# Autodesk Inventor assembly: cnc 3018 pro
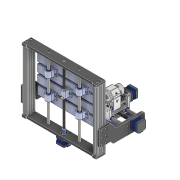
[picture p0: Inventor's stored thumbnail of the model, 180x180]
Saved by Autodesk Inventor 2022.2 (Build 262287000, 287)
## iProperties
Created: 2023-04
Part Number: cnc 3018 pro
Description: STEP AP214
Document SubType Name: Assembly
Designer: 18907419
Sending System: SolidWorks 2023
Preprocessor: SwSTEP 2.0
Title: Baugruppe - Original.STEP
Revision Number: ANY
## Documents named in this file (37)
- C:\Users\18907419\Desktop\cnc 3018\cnc 3018 pro.iam
- C:\Users\18907419\Desktop\cnc 3018\Original - Nutenstein klein M5.ipt
- C:\Users\18907419\Desktop\cnc 3018\Original - Nutenstein M5.ipt
- C:\Users\18907419\Desktop\cnc 3018\Original - Zylinderkopfschraube M4x30.ipt
- C:\Users\18907419\Desktop\cnc 3018\Original - Madenschraube M4x4.ipt
- C:\Users\18907419\Desktop\cnc 3018\Original - Zylinderkopfschraube M3x14.ipt
- C:\Users\18907419\Desktop\cnc 3018\Original - Zylinderkopfschraube M3x20.ipt
- C:\Users\18907419\Desktop\cnc 3018\Original - Zylinderkopfschraube M5x16.ipt
- C:\Users\18907419\Desktop\cnc 3018\Original - Aluminium Profil X.ipt
- C:\Users\18907419\Desktop\cnc 3018\Original - Rahmen X Richtung Y+.ipt
- C:\Users\18907419\Desktop\cnc 3018\Original - Rahmen X Richtung Y-.ipt
- C:\Users\18907419\Desktop\cnc 3018\Original - Aluminium Profil Y.ipt
- C:\Users\18907419\Desktop\cnc 3018\Original - Seitenteil Links.ipt
- C:\Users\18907419\Desktop\cnc 3018\Original - Seitenteil Rechts.ipt
- C:\Users\18907419\Desktop\cnc 3018\Original - Schrittmotor.ipt
- C:\Users\18907419\Desktop\cnc 3018\JST-Steckverbinder-6Pin.ipt
- C:\Users\18907419\Desktop\cnc 3018\Original - Trapezwelle X Achse.ipt
- C:\Users\18907419\Desktop\cnc 3018\Original - Führungswelle Verbinder.ipt
- C:\Users\18907419\Desktop\cnc 3018\Original - KugellagerD16D8H5.ipt
- C:\Users\18907419\Desktop\cnc 3018\Original - T Achse Schrittmotor Träger.ipt
- C:\Users\18907419\Desktop\cnc 3018\Original - Trapezgewindemutter .ipt
- C:\Users\18907419\Desktop\cnc 3018\Original - Trapezgewindemutter Mitnehmer .ipt
- C:\Users\18907419\Desktop\cnc 3018\Original - Trapezgewindemutter Gehäuse.ipt
- C:\Users\18907419\Desktop\cnc 3018\Original - Trapezwelle Y Achse.ipt
- C:\Users\18907419\Desktop\cnc 3018\Original - Spacer Schrittmotor.ipt
- C:\Users\18907419\Desktop\cnc 3018\Original - Trapezwelle Z Achse.ipt
- C:\Users\18907419\Desktop\cnc 3018\Original - Spindelhalter.ipt
- C:\Users\18907419\Desktop\cnc 3018\Original - Kontermutter Spindelhalter.ipt
- C:\Users\18907419\Desktop\cnc 3018\Original - Führungswelle X.ipt
- C:\Users\18907419\Desktop\cnc 3018\Original - LinearlagerA19I10.ipt
- C:\Users\18907419\Desktop\cnc 3018\Original - Linearlager Gehäuse.ipt
- C:\Users\18907419\Desktop\cnc 3018\Original - Führungswelle Y.ipt
- C:\Users\18907419\Desktop\cnc 3018\Original - Führungswelle Z.ipt
- C:\Users\18907419\Desktop\cnc 3018\Original - LinearlagerA15I8.ipt
- C:\Users\18907419\Desktop\cnc 3018\Original - Spindelmotor.ipt
- C:\Users\18907419\Desktop\cnc 3018\Original - Spindelmotor Überwurfmutter.ipt
- C:\Users\18907419\Desktop\cnc 3018\Original - Tisch.ipt
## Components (153 placed, 153 different names)
1. Original - Nutenstein klein M5_1
2. Original - Nutenstein klein M5_2
3. Original - Nutenstein klein M5_3
4. Original - Nutenstein klein M5_4
5. Original - Nutenstein klein M5_5
6. Original - Nutenstein klein M5_6
7. Original - Nutenstein klein M5_7
8. Original - Nutenstein klein M5_8
9. Original - Nutenstein klein M5_9
10. Original - Nutenstein klein M5_10
11. Original - Nutenstein klein M5_11
12. Original - Nutenstein klein M5_12
13. Original - Nutenstein M5_13
14. Original - Nutenstein M5_14
15. Original - Nutenstein M5_15
16. Original - Nutenstein M5_16
17. Original - Nutenstein M5_17
18. Original - Nutenstein M5_18
19. Original - Nutenstein M5_19
20. Original - Nutenstein M5_20
21. Original - Nutenstein M5_21
22. Original - Nutenstein M5_22
23. Original - Zylinderkopfschraube M4x30_23
24. Original - Madenschraube M4x4_24
25. Original - Madenschraube M4x4_25
26. Original - Madenschraube M4x4_26
27. Original - Madenschraube M4x4_27
28. Original - Madenschraube M4x4_28
29. Original - Madenschraube M4x4_29
30. Original - Madenschraube M4x4_30
31. Original - Madenschraube M4x4_31
32. Original - Madenschraube M4x4_32
33. Original - Madenschraube M4x4_33
34. Original - Madenschraube M4x4_34
35. Original - Madenschraube M4x4_35
36. Original - Zylinderkopfschraube M3x14_36
37. Original - Zylinderkopfschraube M3x14_37
38. Original - Zylinderkopfschraube M3x14_38
39. Original - Zylinderkopfschraube M3x14_39
40. Original - Zylinderkopfschraube M3x14_40
41. Original - Zylinderkopfschraube M3x14_41
42. Original - Zylinderkopfschraube M3x14_42
43. Original - Zylinderkopfschraube M3x14_43
44. Original - Zylinderkopfschraube M3x20_44
45. Original - Zylinderkopfschraube M3x20_45
46. Original - Zylinderkopfschraube M3x20_46
47. Original - Zylinderkopfschraube M3x20_47
48. Original - Zylinderkopfschraube M5x16_48
49. Original - Zylinderkopfschraube M5x16_49
50. Original - Zylinderkopfschraube M5x16_50
51. Original - Zylinderkopfschraube M5x16_51
52. Original - Zylinderkopfschraube M5x16_52
53. Original - Zylinderkopfschraube M5x16_53
54. Original - Zylinderkopfschraube M5x16_54
55. Original - Zylinderkopfschraube M5x16_55
56. Original - Zylinderkopfschraube M5x16_56
57. Original - Zylinderkopfschraube M5x16_57
58. Original - Zylinderkopfschraube M5x16_58
59. Original - Zylinderkopfschraube M5x16_59
60. Original - Zylinderkopfschraube M5x16_60
61. Original - Zylinderkopfschraube M5x16_61
62. Original - Zylinderkopfschraube M5x16_62
63. Original - Zylinderkopfschraube M5x16_63
64. Original - Zylinderkopfschraube M5x16_64
65. Original - Zylinderkopfschraube M5x16_65
66. Original - Zylinderkopfschraube M5x16_66
67. Original - Zylinderkopfschraube M5x16_67
68. Original - Zylinderkopfschraube M5x16_68
69. Original - Zylinderkopfschraube M5x16_69
70. Original - Zylinderkopfschraube M5x16_70
71. Original - Zylinderkopfschraube M5x16_71
72. Original - Zylinderkopfschraube M5x16_72
73. Original - Zylinderkopfschraube M5x16_73
74. Original - Zylinderkopfschraube M5x16_74
75. Original - Zylinderkopfschraube M5x16_75
76. Original - Zylinderkopfschraube M5x16_76
77. Original - Zylinderkopfschraube M5x16_77
78. Original - Zylinderkopfschraube M5x16_78
79. Original - Zylinderkopfschraube M5x16_79
80. Original - Zylinderkopfschraube M5x16_80
81. Original - Zylinderkopfschraube M5x16_81
82. Original - Zylinderkopfschraube M5x16_82
83. Original - Zylinderkopfschraube M5x16_83
84. Original - Zylinderkopfschraube M5x16_84
85. Original - Zylinderkopfschraube M5x16_85
86. Original - Zylinderkopfschraube M5x16_86
87. Original - Zylinderkopfschraube M5x16_87
88. Original - Zylinderkopfschraube M5x16_88
89. Original - Zylinderkopfschraube M5x16_89
90. Original - Zylinderkopfschraube M5x16_90
91. Original - Aluminium Profil X_91
92. Original - Aluminium Profil X_92
93. Original - Rahmen X Richtung Y+_93
94. Original - Rahmen X Richtung Y-_94
95. Original - Aluminium Profil Y_95
96. Original - Aluminium Profil Y_96
97. Original - Seitenteil Links_97
98. Original - Seitenteil Rechts_98
99. Original - Schrittmotor_99
100. JST-Steckverbinder-6Pin_100
101. Original - Trapezwelle X Achse_101
102. Original - Führungswelle Verbinder_102
103. Original - KugellagerD16D8H5_103
104. Original - T Achse Schrittmotor Träger_104
105. Original - Trapezgewindemutter _105
106. Original - Trapezgewindemutter Mitnehmer _106
107. Original - Schrittmotor_107
108. JST-Steckverbinder-6Pin_108
109. Original - Trapezgewindemutter _109
110. Original - Trapezgewindemutter Mitnehmer _110
111. Original - Trapezgewindemutter Gehäuse_111
112. Original - Trapezwelle Y Achse_112
113. Original - Führungswelle Verbinder_113
114. Original - KugellagerD16D8H5_114
115. Original - Schrittmotor_115
116. Original - Spacer Schrittmotor_116
117. Original - Spacer Schrittmotor_117
118. Original - Spacer Schrittmotor_118
119. Original - Spacer Schrittmotor_119
120. JST-Steckverbinder-6Pin_120
121. Original - Trapezwelle Z Achse_121
122. Original - Führungswelle Verbinder_122
123. Original - Spindelhalter_123
124. Original - Kontermutter Spindelhalter_124
125. Original - Trapezgewindemutter _125
126. Original - Trapezgewindemutter Mitnehmer _126
127. Original - Führungswelle X_127
128. Original - Führungswelle X_128
129. Original - LinearlagerA19I10_129
130. Original - LinearlagerA19I10_130
131. Original - LinearlagerA19I10_131
132. Original - LinearlagerA19I10_132
133. Original - Linearlager Gehäuse_133
134. Original - LinearlagerA19I10_134
135. Original - Linearlager Gehäuse_135
136. Original - LinearlagerA19I10_136
137. Original - Linearlager Gehäuse_137
138. Original - LinearlagerA19I10_138
139. Original - Linearlager Gehäuse_139
140. Original - LinearlagerA19I10_140
141. Original - Führungswelle Y_141
142. Original - Führungswelle Y_142
143. Original - Führungswelle Z_143
144. Original - Führungswelle Z_144
145. Original - LinearlagerA15I8_145
146. Original - LinearlagerA15I8_146
147. Original - LinearlagerA15I8_147
148. Original - LinearlagerA15I8_148
149. Original - Spindelmotor_149
150. Original - Madenschraube M4x4_150
151. Original - Madenschraube M4x4_151
152. Original - Spindelmotor Überwurfmutter_152
153. Original - Tisch_153
